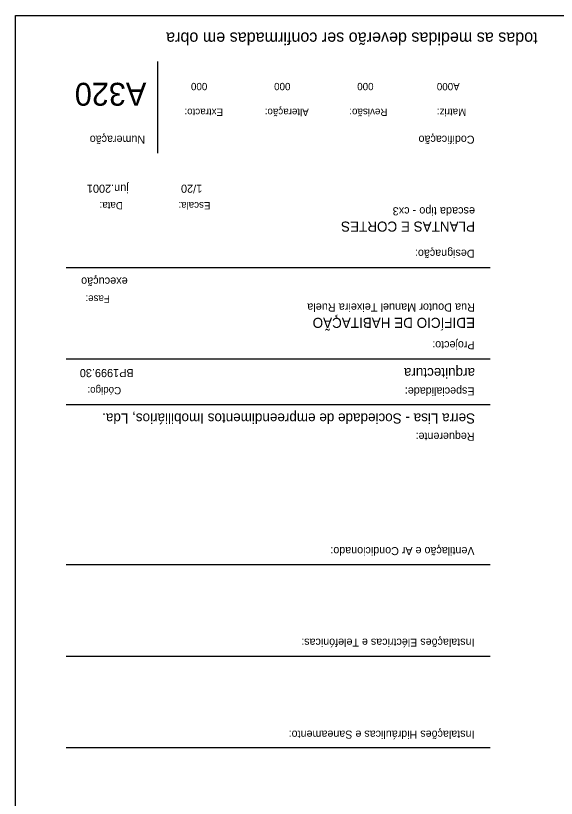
# Model space of a CAD drawing. Extents: x 1295.6 to 1307.2, y -287.2 to -277.8.
# Drawn here: x 1295.594 to 1297.955, y -281.259 to -277.838 of the extents above; entities that cross this region are included whole.
import ezdxf

# ---------------------------------------------------------------- set-up
doc = ezdxf.new("R2010")
doc.units = 0
doc.layers.add('Level 60', color=7, linetype='Continuous')
doc.layers.add('Level 62', color=7, linetype='Continuous')

msp = doc.modelspace()

# ---------------------------------------------------------------- linework, layer by layer
at = {"layer": 'Level 62'}
for p, q in [((1296.21402, -278.03836), (1296.21402, -278.43836)), ((1295.81396, -278.93834), (1297.66596, -278.93834)), ((1295.81396, -279.33834), (1297.66596, -279.33834)), ((1297.66596, -279.53834), (1295.81396, -279.53834)), ((1297.66596, -280.23834), (1295.81396, -280.23834)), ((1297.66596, -280.63834), (1295.81396, -280.63834)), ((1297.66596, -281.03834), (1295.81396, -281.03834))]:
    msp.add_line(p, q, dxfattribs=at)
msp.add_lwpolyline([(1307.19356, -277.83814), (1307.19356, -287.18414), (1295.59396, -287.18414), (1295.59396, -277.83814)], close=True, dxfattribs=at)

# ---------------------------------------------------------------- texts
at = {"layer": 'Level 60'}
msp.add_text('todas as medidas deverão ser confirmadas em obra', height=0.0525996, rotation=180, dxfattribs=at).set_placement((1297.87357, -277.91174))
at = {"layer": 'Level 62'}
for s, height, p in [('A320', 0.09999, (1296.16448, -278.13154)), ('000', 0.031994, (1296.43096, -278.13194)), ('000', 0.032, (1296.79398, -278.13194)), ('000', 0.03199, (1297.15697, -278.13194)), ('A000', 0.032, (1297.53319, -278.13214)), ('Extracto:', 0.031994, (1296.49976, -278.24434)), ('Alteração:', 0.031994, (1296.87416, -278.24434)), ('Revisão:', 0.031994, (1297.21756, -278.24434)), ('Matriz:', 0.031994, (1297.56176, -278.24454)), ('Numeração', 0.034994, (1296.15936, -278.36274)), ('Codificação', 0.0349944, (1297.59796, -278.36254)), ('jun.2001', 0.0356, (1296.08759, -278.57654)), ('1/20', 0.0356, (1296.40868, -278.57654)), ('Data:', 0.031994, (1296.06236, -278.65274)), ('Escala:', 0.031994, (1296.44476, -278.65274)), ('escada tipo - cx3', 0.03559, (1297.60016, -278.67534)), ('PLANTAS E CORTES', 0.04399, (1297.60016, -278.73794)), ('Designação:', 0.0349944, (1297.59796, -278.86074)), ('execução', 0.0356, (1296.08336, -278.98234)), ('Fase:', 0.031994, (1296.00556, -279.06074)), ('Rua Doutor Manuel Teixeira Ruela', 0.03559, (1297.60016, -279.09594)), ('EDIFÍCIO DE HABITAÇÃO', 0.04399, (1297.60016, -279.15854)), ('Projecto:', 0.034994, (1297.59796, -279.26074)), ('arquitectura', 0.0439944, (1297.60016, -279.37794)), ('BP1999.30', 0.0356, (1296.10957, -279.38234)), ('Código:', 0.031994, (1296.05476, -279.46074)), ('Especialidade:', 0.0349944, (1297.59796, -279.46274)), ('Serra Lisa - Sociedade de empreendimentos Imobiliários, Lda.', 0.044, (1297.60036, -279.57654)), ('Requerente:', 0.0349944, (1297.59796, -279.66074)), ('Ventilação e Ar Condicionado:', 0.034998, (1297.59796, -280.16054)), ('Instalações Eléctricas e Telefónicas:', 0.034998, (1297.59796, -280.56054)), ('Instalações Hidráulicas e Saneamento:', 0.034998, (1297.59796, -280.96254))]:
    msp.add_text(s, height=height, rotation=179.99997, dxfattribs=at).set_placement(p)

doc.saveas('drawing.dxf')
